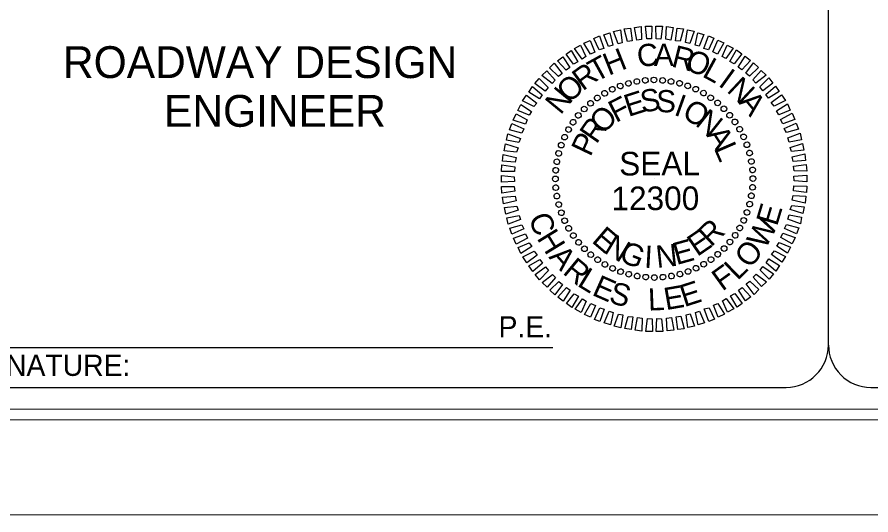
# Model space of a CAD drawing. Extents: x 2105791 to 2114488, y 667759 to 673441.
# Drawn here: x 2112480 to 2113520, y 667759 to 668366 of the extents above; entities that cross this region are included whole.
import ezdxf

# ---------------------------------------------------------------- set-up
doc = ezdxf.new("R2010")
doc.units = 0
for name, color, linetype in [('Sheet PE Seal Cell', 7, 'Continuous'), ('Sheet Plot Border Inside CELL', 7, 'Continuous'), ('Sheet Plot Border Outside CELL', 7, 'Continuous'), ('Sheet Title CELL', 7, 'Continuous')]:
    doc.layers.add(name, color=color, linetype=linetype)

msp = doc.modelspace()

# ---------------------------------------------------------------- linework, layer by layer
at = {"layer": 'Sheet PE Seal Cell'}
for p, q in [((2113214.4, 668282.1), (2113214.4, 668282.1)), ((2113224.4, 668285.2), (2113224.4, 668285.2)), ((2113234.9, 668287.3), (2113234.9, 668287.3)), ((2113245.2, 668289), (2113245.2, 668289)), ((2113255.8, 668289.4), (2113255.8, 668289.4)), ((2113266.4, 668288.9), (2113266.4, 668288.9)), ((2113276.7, 668287.4), (2113276.7, 668287.4)), ((2113286.8, 668285.4), (2113286.8, 668285.4)), ((2113297, 668282.3), (2113297, 668282.3)), ((2113195.6, 668273.1), (2113195.6, 668273.1)), ((2113204.9, 668278.1), (2113204.9, 668278.1)), ((2113306.7, 668278.1), (2113306.7, 668278.1)), ((2113316.1, 668273.5), (2113316.1, 668273.5)), ((2113178.3, 668261.3), (2113178.3, 668261.3)), ((2113186.6, 668267.4), (2113186.6, 668267.4)), ((2113324.9, 668267.7), (2113324.9, 668267.7)), ((2113333.4, 668261.4), (2113333.4, 668261.4)), ((2113170.5, 668253.9), (2113170.5, 668253.9)), ((2113341, 668254.3), (2113341, 668254.3)), ((2113163.5, 668246.3), (2113163.5, 668246.3)), ((2113348.3, 668246.5), (2113348.3, 668246.5)), ((2113354.5, 668238.3), (2113354.5, 668238.3)), ((2113151.3, 668229.1), (2113151.3, 668229.1)), ((2113157.2, 668237.8), (2113157.2, 668237.8)), ((2113360.2, 668229.2), (2113360.2, 668229.2)), ((2113146.7, 668219.6), (2113146.7, 668219.6)), ((2113365.1, 668220), (2113365.1, 668220)), ((2113142.6, 668209.9), (2113142.6, 668209.9)), ((2113369.2, 668210.4), (2113369.2, 668210.4)), ((2113139.4, 668199.8), (2113139.4, 668199.8)), ((2113372.2, 668200.4), (2113372.2, 668200.4)), ((2113137.4, 668189.7), (2113137.4, 668189.7)), ((2113374.4, 668189.9), (2113374.4, 668189.9)), ((2113136, 668179.3), (2113136, 668179.3)), ((2113376, 668179.6), (2113376, 668179.6)), ((2113135.4, 668168.7), (2113135.4, 668168.7)), ((2113255.9, 668168.9), (2113255.9, 668168.9)), ((2113376.4, 668169.1), (2113376.4, 668169.1)), ((2113135.9, 668158.2), (2113135.9, 668158.2)), ((2113375.9, 668158.5), (2113375.9, 668158.5)), ((2113137.5, 668147.9), (2113137.5, 668147.9)), ((2113374.5, 668148.1), (2113374.5, 668148.1)), ((2113139.7, 668137.4), (2113139.7, 668137.4)), ((2113372.5, 668138), (2113372.5, 668138)), ((2113142.7, 668127.4), (2113142.7, 668127.4)), ((2113369.3, 668127.9), (2113369.3, 668127.9)), ((2113146.8, 668117.8), (2113146.8, 668117.8)), ((2113365.2, 668118.2), (2113365.2, 668118.2)), ((2113151.7, 668108.6), (2113151.7, 668108.6)), ((2113360.6, 668108.7), (2113360.6, 668108.7)), ((2113157.4, 668099.5), (2113157.4, 668099.5)), ((2113354.7, 668100), (2113354.7, 668100)), ((2113163.6, 668091.3), (2113163.6, 668091.3)), ((2113170.9, 668083.5), (2113170.9, 668083.5)), ((2113341.4, 668083.9), (2113341.4, 668083.9)), ((2113348.4, 668091.5), (2113348.4, 668091.5)), ((2113178.5, 668076.4), (2113178.5, 668076.4)), ((2113333.6, 668076.5), (2113333.6, 668076.5)), ((2113187, 668070.1), (2113187, 668070.1)), ((2113195.8, 668064.3), (2113195.8, 668064.3)), ((2113316.3, 668064.7), (2113316.3, 668064.7)), ((2113325.3, 668070.4), (2113325.3, 668070.4)), ((2113205.2, 668059.7), (2113205.2, 668059.7)), ((2113214.9, 668055.5), (2113214.9, 668055.5)), ((2113225.1, 668052.4), (2113225.1, 668052.4)), ((2113287.5, 668052.6), (2113287.5, 668052.6)), ((2113297.5, 668055.7), (2113297.5, 668055.7)), ((2113307, 668059.7), (2113307, 668059.7)), ((2113235.2, 668050.4), (2113235.2, 668050.4)), ((2113245.5, 668048.9), (2113245.5, 668048.9)), ((2113256.1, 668048.4), (2113256.1, 668048.4)), ((2113266.7, 668048.8), (2113266.7, 668048.8)), ((2113277, 668050.5), (2113277, 668050.5))]:
    msp.add_line(p, q, dxfattribs=at)
for points in [[(2113234.9, 668338), (2113232, 668353.3), (2113240.1, 668354.4), (2113240.7, 668338.8)], [(2113246.9, 668339.4), (2113245.4, 668355), (2113253.3, 668354.9), (2113252.7, 668339.3)], [(2113258.4, 668339.4), (2113258.1, 668355), (2113266, 668354.9), (2113264.2, 668339.2)], [(2113270.4, 668338.9), (2113271.1, 668354.5), (2113279, 668353.2), (2113276.2, 668338)], [(2113188.8, 668326), (2113182.3, 668339.8), (2113189.5, 668342.9), (2113194.8, 668327.6)], [(2113200.5, 668330.1), (2113194.7, 668344.4), (2113202.1, 668346.7), (2113205.5, 668331.9)], [(2113212, 668333.4), (2113206.6, 668348.5), (2113214.8, 668350.3), (2113217, 668334.7)], [(2113223.4, 668336.3), (2113219.3, 668351.6), (2113227.2, 668352.5), (2113229.2, 668337.1)], [(2113282, 668337.2), (2113283.9, 668352.6), (2113291.8, 668351.5), (2113287.8, 668336.6)], [(2113294.3, 668334.8), (2113296.4, 668350.4), (2113304.6, 668348.7), (2113299.3, 668333.7)], [(2113305.9, 668331.9), (2113309.2, 668346.8), (2113316.7, 668344.6), (2113310.9, 668330.3)], [(2113316.7, 668327.8), (2113322, 668343), (2113328.7, 668340.3), (2113322.3, 668326.2)], [(2113178.4, 668320.8), (2113170.4, 668334.1), (2113177.8, 668337.6), (2113183.6, 668323.1)], [(2113327.6, 668323.4), (2113333.4, 668337.7), (2113340.9, 668334.5), (2113333, 668320.9)], [(2113338.8, 668318.1), (2113345, 668331.9), (2113352.3, 668328), (2113343.4, 668315.3)], [(2113157.7, 668308.6), (2113148.6, 668320.7), (2113154.8, 668325.4), (2113162.9, 668311.6)], [(2113168.2, 668314.8), (2113159, 668327.6), (2113166.4, 668331.6), (2113172.7, 668317.8)], [(2113348.3, 668311.8), (2113356.4, 668325.9), (2113362.7, 668321), (2113353.6, 668309)], [(2113148.7, 668301.3), (2113138.2, 668312.6), (2113144.6, 668317.7), (2113153.2, 668304.5)], [(2113358.2, 668304.8), (2113366.9, 668318.2), (2113373.2, 668313), (2113362.9, 668301.5)], [(2113139.3, 668293.6), (2113128.5, 668304), (2113134.2, 668309.9), (2113143.8, 668297.1)], [(2113367.5, 668297.6), (2113377.1, 668310.2), (2113383, 668304.6), (2113372.1, 668294)], [(2113376.3, 668289.3), (2113386.4, 668300.8), (2113392.3, 668295.1), (2113380, 668285.6)], [(2113123.3, 668275.8), (2113110.6, 668284.9), (2113115.8, 668291.3), (2113126.6, 668280.2)], [(2113131.5, 668285.1), (2113119.1, 668294.7), (2113125, 668300.3), (2113135.3, 668289)], [(2113384.9, 668280.8), (2113395.7, 668291.9), (2113400.8, 668285.5), (2113388.3, 668276.1)], [(2113116.3, 668266.5), (2113103.2, 668274.5), (2113107.6, 668281.5), (2113119.3, 668271.2)], [(2113392.2, 668271.6), (2113403.8, 668281.9), (2113408.5, 668275.1), (2113395.2, 668267.1)], [(2113109.3, 668256.8), (2113095.7, 668263.7), (2113100.4, 668270.6), (2113113, 668261.2)], [(2113398.7, 668261.9), (2113411.2, 668271.3), (2113415.9, 668264.2), (2113402.1, 668257.2)], [(2113103.7, 668246.4), (2113089.9, 668252.1), (2113093.4, 668259.6), (2113106.5, 668251)], [(2113405.1, 668251.5), (2113418.4, 668260.1), (2113421.6, 668252.7), (2113408.1, 668247)], [(2113410.1, 668241.2), (2113424.1, 668248.7), (2113427.4, 668241.1), (2113412.6, 668236)], [(2113099.1, 668235.3), (2113084.1, 668240.5), (2113087.6, 668248), (2113101.4, 668240.6)], [(2113094.5, 668224.6), (2113079.6, 668228.6), (2113082.5, 668236.1), (2113097.1, 668229.7)], [(2113414.6, 668230), (2113429.2, 668236.6), (2113431.9, 668229.2), (2113417.1, 668225.1)], [(2113091.1, 668213), (2113076.2, 668215.8), (2113077.7, 668223.8), (2113093, 668218.1)], [(2113418.7, 668218.6), (2113434, 668224.4), (2113435.5, 668216.5), (2113420.5, 668213.6)], [(2113088.3, 668201.4), (2113073.3, 668203.1), (2113074.9, 668211.3), (2113090.1, 668206.5)], [(2113421.8, 668207.1), (2113436.8, 668212), (2113438.4, 668203.9), (2113423.3, 668202.1)], [(2113086.6, 668189.2), (2113071.2, 668190.3), (2113072, 668198.5), (2113087.7, 668194.9)], [(2113424.2, 668195.7), (2113439.7, 668199.3), (2113440.6, 668191.2), (2113425.3, 668189.9)], [(2113425.8, 668184.2), (2113441.4, 668186.4), (2113442, 668178.2), (2113426.4, 668178.4)], [(2113085.6, 668177.6), (2113070, 668177.8), (2113070.3, 668185.7), (2113086, 668183.4)], [(2113085.6, 668165.6), (2113070, 668164.6), (2113069.8, 668172.8), (2113085.5, 668171.4)], [(2113426.3, 668172.2), (2113441.9, 668173.2), (2113442.1, 668165), (2113426.4, 668166.4)], [(2113086.1, 668153.6), (2113070.5, 668151.4), (2113069.9, 668159.6), (2113085.5, 668159.4)], [(2113426.3, 668160.2), (2113441.9, 668160), (2113441.6, 668152.1), (2113425.9, 668154.4)], [(2113087.7, 668142.1), (2113072.2, 668138.5), (2113071.3, 668146.6), (2113086.6, 668147.9)], [(2113425.3, 668148.6), (2113440.7, 668147.5), (2113439.9, 668139.3), (2113424.2, 668142.9)], [(2113090.1, 668130.7), (2113075.1, 668125.8), (2113073.5, 668133.9), (2113088.6, 668135.7)], [(2113423.6, 668136.4), (2113438.6, 668134.7), (2113437, 668126.5), (2113421.8, 668131.3)], [(2113093.2, 668119.2), (2113077.9, 668113.4), (2113076.4, 668121.3), (2113091.4, 668124.2)], [(2113420.7, 668124.8), (2113435.7, 668122), (2113434.2, 668114), (2113418.9, 668119.7)], [(2113097.3, 668107.8), (2113082.7, 668101.2), (2113080, 668108.6), (2113094.8, 668112.7)], [(2113417.4, 668113.2), (2113432.3, 668109.2), (2113429.4, 668101.7), (2113414.8, 668108.1)], [(2113101.8, 668096.6), (2113087.8, 668089.1), (2113084.5, 668096.7), (2113099.3, 668101.8)], [(2113412.8, 668102.5), (2113427.8, 668097.3), (2113424.3, 668089.8), (2113410.5, 668097.2)], [(2113106.8, 668086.3), (2113093.5, 668077.7), (2113090.3, 668085.1), (2113103.8, 668090.8)], [(2113408.2, 668091.4), (2113422, 668085.7), (2113418.5, 668078.2), (2113405.4, 668086.8)], [(2113113.2, 668075.9), (2113100.7, 668066.5), (2113096, 668073.6), (2113109.8, 668080.6)], [(2113402.6, 668081), (2113416.2, 668074), (2113411.5, 668067.2), (2113398.9, 668076.6)], [(2113119.7, 668066.2), (2113108.1, 668055.9), (2113103.4, 668062.7), (2113116.7, 668070.7)], [(2113127, 668057), (2113116.2, 668045.9), (2113111, 668052.3), (2113123.6, 668061.7)], [(2113388.6, 668062), (2113401.3, 668052.9), (2113396.1, 668046.5), (2113385.3, 668057.6)], [(2113395.6, 668071.3), (2113408.7, 668063.3), (2113404.3, 668056.3), (2113392.6, 668066.6)], [(2113135.6, 668048.5), (2113125.5, 668037), (2113119.6, 668042.6), (2113131.9, 668052.2)], [(2113380.4, 668052.7), (2113392.8, 668043.1), (2113386.9, 668037.5), (2113376.6, 668048.8)], [(2113144.4, 668040.2), (2113134.8, 668027.6), (2113128.9, 668033.2), (2113139.8, 668043.8)], [(2113372.6, 668044.2), (2113383.4, 668033.8), (2113377.7, 668027.9), (2113368.1, 668040.7)], [(2113153.7, 668033), (2113145, 668019.6), (2113138.7, 668024.8), (2113149, 668036.3)], [(2113363.2, 668036.5), (2113373.7, 668025.2), (2113367.3, 668020.1), (2113358.7, 668033.3)], [(2113163.6, 668026), (2113155.5, 668011.9), (2113149.2, 668016.8), (2113158.3, 668028.8)], [(2113173.1, 668019.7), (2113166.9, 668005.9), (2113159.6, 668009.8), (2113168.5, 668022.5)], [(2113343.7, 668023), (2113352.9, 668010.2), (2113345.5, 668006.2), (2113339.2, 668020)], [(2113354.2, 668029.2), (2113363.3, 668017.1), (2113357.1, 668012.4), (2113349, 668026.2)], [(2113184.3, 668014.4), (2113178.5, 668000.1), (2113171, 668003.3), (2113178.9, 668016.9)], [(2113195.2, 668010), (2113189.9, 667994.8), (2113183.2, 667997.5), (2113189.6, 668011.6)], [(2113323.1, 668011.8), (2113329.6, 667998), (2113322.4, 667994.9), (2113317.1, 668010.2)], [(2113333.5, 668017), (2113341.5, 668003.7), (2113334.1, 668000.2), (2113328.3, 668014.7)], [(2113206, 668005.9), (2113202.7, 667991), (2113195.2, 667993.2), (2113201, 668007.5)], [(2113217.6, 668003), (2113215.5, 667987.4), (2113207.3, 667989.1), (2113212.6, 668004.1)], [(2113229.9, 668000.6), (2113228, 667985.2), (2113220.1, 667986.3), (2113224.1, 668001.2)], [(2113241.5, 667998.9), (2113240.8, 667983.3), (2113232.9, 667984.6), (2113235.7, 667999.8)], [(2113277, 667999.8), (2113279.9, 667984.5), (2113271.8, 667983.4), (2113271.2, 667999)], [(2113288.5, 668001.5), (2113292.6, 667986.2), (2113284.7, 667985.3), (2113282.7, 668000.7)], [(2113299.9, 668004.4), (2113305.3, 667989.3), (2113297.1, 667987.5), (2113294.9, 668003.1)], [(2113311.4, 668007.7), (2113317.2, 667993.4), (2113309.8, 667991.1), (2113306.4, 668005.9)], [(2113253.5, 667998.4), (2113253.8, 667982.8), (2113245.8, 667982.9), (2113247.7, 667998.5)], [(2113265, 667998.4), (2113266.5, 667982.8), (2113258.6, 667982.9), (2113259.2, 667998.5)]]:
    msp.add_lwpolyline(points, close=True, dxfattribs=at)
for centre, major_axis in [((2113234.8, 668287.4), (-0.61, 3.4)), ((2113245.2, 668288.8), (-0.31, 3.44)), ((2113255.7, 668289.3), (-0.01, 3.46)), ((2113266.2, 668288.8), (0.29, 3.44)), ((2113276.6, 668287.5), (0.59, 3.4)), ((2113204.9, 668277.9), (-1.47, 3.13)), ((2113214.6, 668281.9), (-1.19, 3.25)), ((2113224.6, 668285.1), (-0.9, 3.34)), ((2113286.9, 668285.2), (0.89, 3.34)), ((2113296.9, 668282.1), (1.18, 3.25)), ((2113306.6, 668278.1), (1.45, 3.13)), ((2113186.7, 668267.4), (-1.99, 2.83)), ((2113195.6, 668273), (-1.73, 2.99)), ((2113316, 668273.3), (1.72, 3)), ((2113324.8, 668267.6), (1.98, 2.83)), ((2113178.4, 668261), (-2.23, 2.64)), ((2113333.2, 668261.3), (2.22, 2.65)), ((2113163.6, 668246.1), (-2.65, 2.22)), ((2113170.7, 668253.9), (-2.45, 2.44)), ((2113340.9, 668254.2), (2.44, 2.45)), ((2113348, 668246.4), (2.64, 2.23)), ((2113157.2, 668237.8), (-2.83, 1.98)), ((2113354.4, 668238.1), (2.83, 1.99)), ((2113151.6, 668228.9), (-3, 1.72)), ((2113360.1, 668229.3), (2.99, 1.73)), ((2113146.8, 668219.6), (-3.13, 1.45)), ((2113365, 668220), (3.13, 1.47)), ((2113142.7, 668209.9), (-3.25, 1.18)), ((2113369, 668210.3), (3.25, 1.19)), ((2113139.6, 668199.8), (-3.34, 0.89)), ((2113372.2, 668200.3), (3.34, 0.9)), ((2113137.4, 668189.6), (-3.4, 0.59)), ((2113374.5, 668190), (3.4, 0.61)), ((2113136, 668179.2), (-3.44, 0.29)), ((2113375.9, 668179.6), (3.44, 0.31)), ((2113135.6, 668168.7), (-3.46, -0.01)), ((2113376.3, 668169.1), (3.46, 0.01)), ((2113136, 668158.2), (-3.44, -0.31)), ((2113375.9, 668158.6), (3.44, -0.29)), ((2113137.4, 668147.8), (-3.4, -0.61)), ((2113374.5, 668148.2), (3.4, -0.59)), ((2113139.7, 668137.5), (-3.34, -0.9)), ((2113372.3, 668138), (3.34, -0.89)), ((2113142.9, 668127.5), (-3.25, -1.19)), ((2113369.1, 668127.9), (3.25, -1.18)), ((2113146.9, 668117.8), (-3.13, -1.47)), ((2113365.1, 668118.2), (3.13, -1.45)), ((2113151.8, 668108.5), (-2.99, -1.73)), ((2113157.5, 668099.7), (-2.83, -1.99)), ((2113354.7, 668100), (2.83, -1.98)), ((2113360.3, 668108.9), (3, -1.72)), ((2113163.9, 668091.4), (-2.64, -2.23)), ((2113348.3, 668091.7), (2.65, -2.22)), ((2113171, 668083.6), (-2.44, -2.45)), ((2113341.2, 668083.9), (2.45, -2.44)), ((2113178.7, 668076.5), (-2.22, -2.65)), ((2113187.1, 668070.2), (-1.98, -2.83)), ((2113325.2, 668070.4), (1.99, -2.83)), ((2113333.5, 668076.8), (2.23, -2.64)), ((2113195.9, 668064.5), (-1.72, -3)), ((2113205.3, 668059.7), (-1.45, -3.13)), ((2113307, 668059.9), (1.47, -3.13)), ((2113316.3, 668064.8), (1.73, -2.99)), ((2113215, 668055.7), (-1.18, -3.25)), ((2113225, 668052.6), (-0.89, -3.34)), ((2113235.3, 668050.3), (-0.59, -3.4)), ((2113245.7, 668049), (-0.29, -3.44)), ((2113256.2, 668048.5), (0.01, -3.46)), ((2113266.7, 668049), (0.31, -3.44)), ((2113277.1, 668050.4), (0.61, -3.4)), ((2113287.3, 668052.7), (0.9, -3.34)), ((2113297.3, 668055.9), (1.19, -3.25))]:
    msp.add_ellipse(centre, major_axis=major_axis, ratio=0.999708, dxfattribs=at)
at = {"layer": 'Sheet Plot Border Inside CELL'}
msp.add_lwpolyline([(2105858.2, 667876.6), (2114463.6, 667875.1), (2114464.5, 673323.4), (2105859.1, 673324.8)], close=True, dxfattribs=at)
at = {"layer": 'Sheet Plot Border Outside CELL'}
msp.add_lwpolyline([(2114487.7, 673439.3), (2105792, 673440.8), (2105791, 667760.7), (2114486.8, 667759.2)], close=True, dxfattribs=at)
at = {"layer": 'Sheet Title CELL'}
for p, q in [((2113468.4, 667966), (2113468.5, 668792.2)), ((2113468.4, 667966), (2113468.5, 668792.2)), ((2112401.9, 667963.3), (2113132.6, 667963.1)), ((2112370.6, 667914.5), (2113416.7, 667914.6)), ((2113520, 667914.6), (2114321.6, 667914.4))]:
    msp.add_line(p, q, dxfattribs=at)
msp.add_lwpolyline([(2106705, 667889.6), (2114347.4, 667888.3)], dxfattribs=at)
for centre, start, end in [((2113416.7, 667966.3), 269.9903, 359.9903), ((2113520, 667966.3), 179.9903, 269.9903), ((2113520, 667966.3), 179.9903, 269.9903)]:
    msp.add_arc(centre, 51.6, start, end, dxfattribs=at)

# ---------------------------------------------------------------- texts
at = {"layer": 'Sheet PE Seal Cell'}
for s, height, rotation, p in [('C', 27.1, 7.3238, (2113236.8, 668304.6)), ('A', 27.1, 0.1243, (2113255.7, 668306.4)), ('H', 27.1, 21.7235, (2113200.5, 668294.3)), ('R', 27.1, 345.7251, (2113275.9, 668305.9)), ('O', 27.1, 338.5251, (2113292, 668302.6)), ('T', 27.1, 28.9237, (2113185, 668286.1)), ('L', 27.1, 331.3248, (2113313.3, 668294.1)), ('R', 27.1, 36.1245, (2113168.9, 668275.2)), ('I', 27.1, 324.1241, (2113333, 668283)), ('O', 27.1, 43.3257, (2113152.7, 668260)), ('N', 27.1, 316.9229, (2113343.4, 668275.7)), ('N', 27.1, 50.5275, (2113141.9, 668245.9)), ('F', 27.1, 27.071, (2113209.3, 668236.7)), ('E', 27.1, 17.715, (2113224.5, 668244.1)), ('S', 27.1, 8.3596, (2113241, 668249.5)), ('S', 27.1, 359.0044, (2113258.2, 668250.1)), ('I', 27.1, 340.2936, (2113278.9, 668247.1)), ('A', 27.1, 309.7211, (2113357.9, 668261.8)), ('O', 27.1, 330.9375, (2113288.6, 668243.9)), ('O', 27.1, 45.7852, (2113193.7, 668222.2)), ('N', 27.1, 321.5806, (2113304.9, 668234.7)), ('R', 27.1, 55.1436, (2113185.5, 668210.3)), ('A', 27.1, 302.8642, (2113318.8, 668222.4)), ('P', 27.1, 64.5029, (2113178.2, 668194.8)), ('L', 27.1, 293.5048, (2113328.4, 668206.1)), ('SEAL', 28.79, 0.104, (2113213.4, 668172.9)), ('12300', 28.8, 0.104, (2113203.9, 668130.6)), ('E', 27.1, 73.3356, (2113405.7, 668110.2)), ('C', 27.1, 291.9912, (2113102.3, 668121.2)), ('W', 27.1, 62.0852, (2113391.4, 668082.1)), ('R', 27.1, 43.5854, (2113325.3, 668085)), ('H', 27.1, 301.5037, (2113112.3, 668096.5)), ('E', 27.1, 319.3809, (2113178.7, 668092.3)), ('E', 27.1, 34.2281, (2113308.4, 668073.4)), ('N', 27.1, 328.7379, (2113193.3, 668079.6)), ('E', 27.1, 15.5157, (2113283.2, 668063.6)), ('A', 27.1, 311.2528, (2113126.7, 668073.2)), ('G', 27.1, 338.0942, (2113211.8, 668069.1)), ('I', 27.1, 356.8052, (2113243.4, 668060.6)), ('N', 27.1, 6.1604, (2113259.5, 668060.2)), ('O', 27.1, 51.408, (2113372.9, 668058.5)), ('R', 27.1, 320.3285, (2113143.4, 668054)), ('F', 27.1, 35.8407, (2113339, 668031.2)), ('L', 27.1, 43.8427, (2113357.4, 668044.1)), ('L', 27.1, 328.6035, (2113161.1, 668039)), ('E', 27.1, 336.1687, (2113179, 668027.7)), ('S', 27.1, 344.2254, (2113199.6, 668018.3)), ('E', 27.1, 17.9077, (2113292.6, 668012.3)), ('L', 27.1, 2.2858, (2113249, 668008.2)), ('E', 27.1, 9.8511, (2113270.3, 668008.7))]:
    msp.add_text(s, height=height, rotation=rotation, dxfattribs=at).set_placement(p)
at = {"layer": 'Sheet Title CELL'}
for s, height, p in [('ROADWAY DESIGN', 38.725, (2112535.5, 668291.7)), ('ENGINEER', 38.73, (2112658.6, 668232.3)), ('P.E.', 25.82, (2113066.3, 667975.6)), ('SIGNATURE:', 25.82, (2112406.6, 667928.7))]:
    msp.add_text(s, height=height, rotation=359.9903, dxfattribs=at).set_placement(p)

doc.saveas('drawing.dxf')
